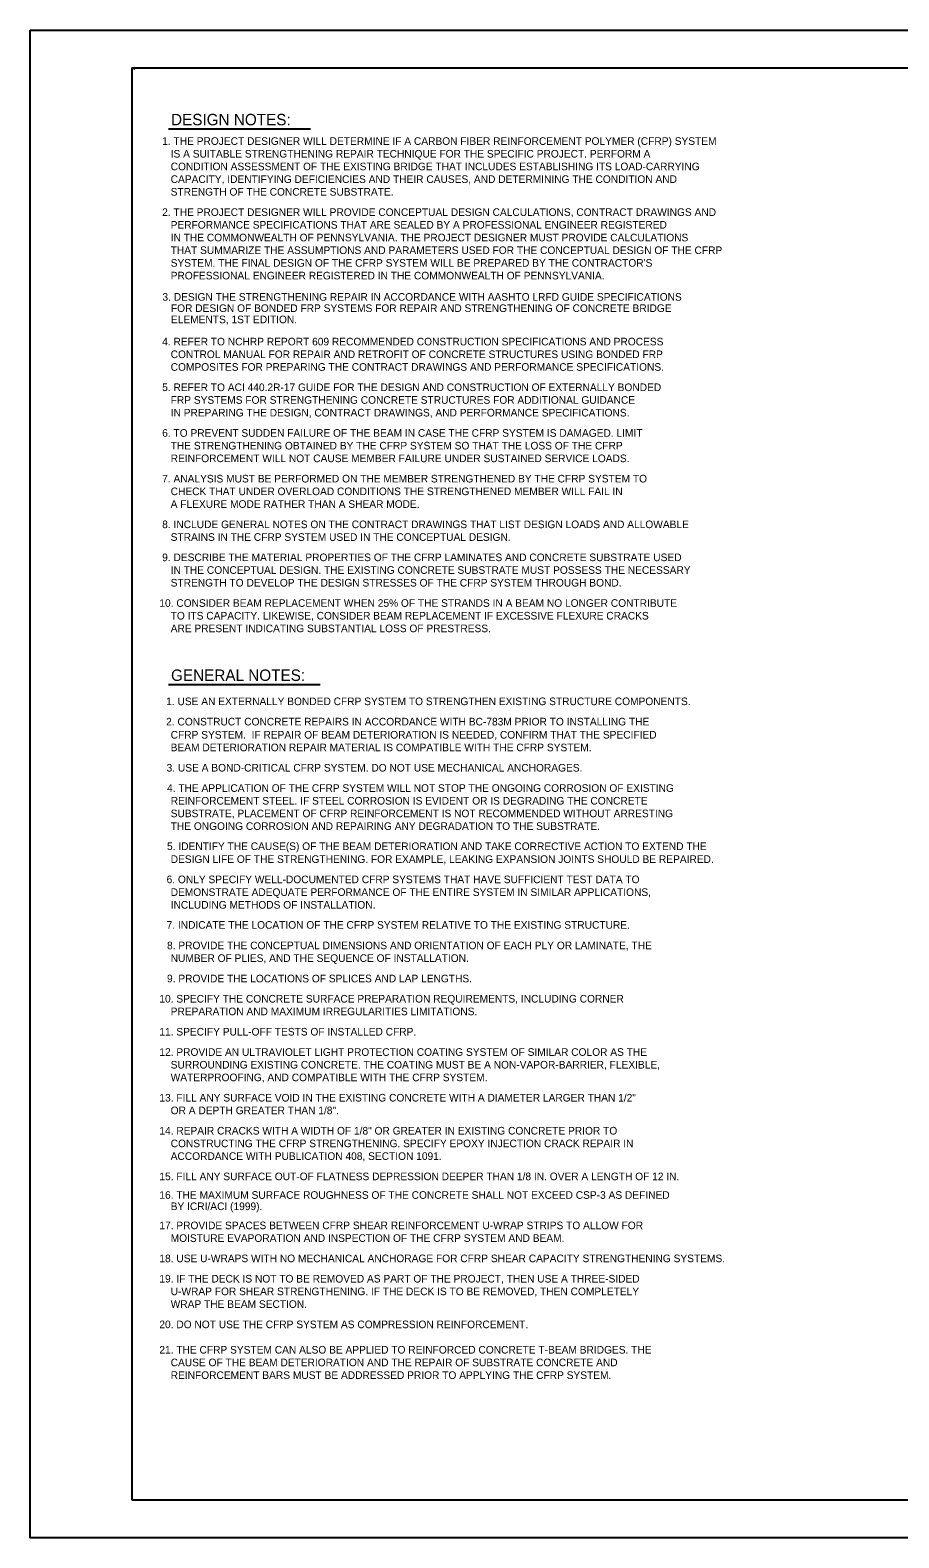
# Model space of a CAD drawing. Extents: x -875 to -19, y -633 to -39.
# Drawn here: x -875 to -532, y -633 to -39 of the extents above; entities that cross this region are included whole.
import ezdxf

# ---------------------------------------------------------------- set-up
doc = ezdxf.new("R2010")
doc.units = 0
for name, color, linetype in [('1', 7, 'Continuous'), ('2', 7, 'Continuous'), ('PLT-BNDY', 7, 'Continuous')]:
    doc.layers.add(name, color=color, linetype=linetype)

msp = doc.modelspace()

# ---------------------------------------------------------------- linework, layer by layer
at = {"layer": '1'}
for p, q in [((-48.54, -54.21), (-834.54, -54.21)), ((-834.54, -54.21), (-834.54, -618.21)), ((-834.54, -618.21), (-48.54, -618.21))]:
    msp.add_line(p, q, dxfattribs=at)
at = {"layer": '2'}
for p, q in [((-48.54, -54.21), (-834.54, -54.21)), ((-834.54, -54.89), (-834.54, -54.89)), ((-820.06, -78.13), (-764.06, -78.13)), ((-820.06, -297.01), (-760.25, -297.01))]:
    msp.add_line(p, q, dxfattribs=at)
msp.add_lwpolyline([(-833.19, -54.55), (-834.54, -54.21), (-833.19, -53.87)], dxfattribs=at)
at = {"layer": 'PLT-BNDY'}
msp.add_lwpolyline([(-874.54, -39.21), (-33.54, -39.21), (-33.54, -633.21), (-874.54, -633.21)], close=True, dxfattribs=at)

# ---------------------------------------------------------------- texts
at = {"layer": '2'}
for s, height, p in [('DESIGN NOTES:', 4.5, (-819.03, -76.69)), (' 1. THE PROJECT DESIGNER WILL DETERMINE IF A CARBON FIBER REINFORCEMENT POLYMER (CFRP) SYSTEM', 3, (-823.63, -84.41)), ('    IS A SUITABLE STRENGTHENING REPAIR TECHNIQUE FOR THE SPECIFIC PROJECT. PERFORM A', 3, (-823.63, -89.41)), ('    CONDITION ASSESSMENT OF THE EXISTING BRIDGE THAT INCLUDES ESTABLISHING ITS LOAD-CARRYING', 3, (-823.63, -94.41)), ('    CAPACITY, IDENTIFYING DEFICIENCIES AND THEIR CAUSES, AND DETERMINING THE CONDITION AND', 3, (-823.63, -99.41)), ('    STRENGTH OF THE CONCRETE SUBSTRATE.', 3, (-823.63, -104.41)), (' 2. THE PROJECT DESIGNER WILL PROVIDE CONCEPTUAL DESIGN CALCULATIONS, CONTRACT DRAWINGS AND', 3, (-823.63, -112.41)), ('    PERFORMANCE SPECIFICATIONS THAT ARE SEALED BY A PROFESSIONAL ENGINEER REGISTERED', 3, (-823.63, -117.41)), ('    THAT SUMMARIZE THE ASSUMPTIONS AND PARAMETERS USED FOR THE CONCEPTUAL DESIGN OF THE CFRP', 3, (-823.63, -127.41)), ('    IN THE COMMONWEALTH OF PENNSYLVANIA. THE PROJECT DESIGNER MUST PROVIDE CALCULATIONS', 3, (-823.63, -122.41)), ("    SYSTEM. THE FINAL DESIGN OF THE CFRP SYSTEM WILL BE PREPARED BY THE CONTRACTOR'S", 3, (-823.63, -132.41)), ('    PROFESSIONAL ENGINEER REGISTERED IN THE COMMONWEALTH OF PENNSYLVANIA.', 3, (-823.63, -137.41)), (' 3. DESIGN THE STRENGTHENING REPAIR IN ACCORDANCE WITH AASHTO LRFD GUIDE SPECIFICATIONS', 3, (-823.53, -145.8)), ('    FOR DESIGN OF BONDED FRP SYSTEMS FOR REPAIR AND STRENGTHENING OF CONCRETE BRIDGE', 3, (-823.53, -150.24)), ('    ELEMENTS, 1ST EDITION.', 3, (-823.53, -154.68)), (' 4. REFER TO NCHRP REPORT 609 RECOMMENDED CONSTRUCTION SPECIFICATIONS AND PROCESS', 3, (-823.63, -163.41)), ('    CONTROL MANUAL FOR REPAIR AND RETROFIT OF CONCRETE STRUCTURES USING BONDED FRP', 3, (-823.63, -168.41)), ('    COMPOSITES FOR PREPARING THE CONTRACT DRAWINGS AND PERFORMANCE SPECIFICATIONS.', 3, (-823.63, -173.41)), (' 5. REFER TO ACI 440.2R-17 GUIDE FOR THE DESIGN AND CONSTRUCTION OF EXTERNALLY BONDED', 3, (-823.63, -181.41)), ('    FRP SYSTEMS FOR STRENGTHENING CONCRETE STRUCTURES FOR ADDITIONAL GUIDANCE', 3, (-823.63, -186.41)), ('    IN PREPARING THE DESIGN, CONTRACT DRAWINGS, AND PERFORMANCE SPECIFICATIONS.', 3, (-823.63, -191.41)), (' 6. TO PREVENT SUDDEN FAILURE OF THE BEAM IN CASE THE CFRP SYSTEM IS DAMAGED. LIMIT', 3, (-823.63, -199.41)), ('    THE STRENGTHENING OBTAINED BY THE CFRP SYSTEM SO THAT THE LOSS OF THE CFRP', 3, (-823.63, -204.41)), ('    REINFORCEMENT WILL NOT CAUSE MEMBER FAILURE UNDER SUSTAINED SERVICE LOADS.', 3, (-823.63, -209.41)), (' 7. ANALYSIS MUST BE PERFORMED ON THE MEMBER STRENGTHENED BY THE CFRP SYSTEM TO', 3, (-823.63, -217.41)), ('    CHECK THAT UNDER OVERLOAD CONDITIONS THE STRENGTHENED MEMBER WILL FAIL IN', 3, (-823.63, -222.41)), ('    A FLEXURE MODE RATHER THAN A SHEAR MODE.', 3, (-823.63, -227.41)), (' 8. INCLUDE GENERAL NOTES ON THE CONTRACT DRAWINGS THAT LIST DESIGN LOADS AND ALLOWABLE', 3, (-823.63, -235.41)), ('    STRAINS IN THE CFRP SYSTEM USED IN THE CONCEPTUAL DESIGN.', 3, (-823.63, -240.41)), (' 9. DESCRIBE THE MATERIAL PROPERTIES OF THE CFRP LAMINATES AND CONCRETE SUBSTRATE USED', 3, (-823.63, -248.41)), ('    STRENGTH TO DEVELOP THE DESIGN STRESSES OF THE CFRP SYSTEM THROUGH BOND.', 3, (-823.63, -258.41)), ('    IN THE CONCEPTUAL DESIGN. THE EXISTING CONCRETE SUBSTRATE MUST POSSESS THE NECESSARY', 3, (-823.63, -253.41)), ('10. CONSIDER BEAM REPLACEMENT WHEN 25% OF THE STRANDS IN A BEAM NO LONGER CONTRIBUTE', 3, (-823.63, -266.41)), ('    TO ITS CAPACITY. LIKEWISE, CONSIDER BEAM REPLACEMENT IF EXCESSIVE FLEXURE CRACKS', 3, (-823.63, -271.41)), ('    ARE PRESENT INDICATING SUBSTANTIAL LOSS OF PRESTRESS. ', 3, (-823.63, -276.41)), ('GENERAL NOTES:', 4.5, (-819.03, -295.59)), ('1. USE AN EXTERNALLY BONDED CFRP SYSTEM TO STRENGTHEN EXISTING STRUCTURE COMPONENTS.', 3, (-820.95, -305.14)), ('2. CONSTRUCT CONCRETE REPAIRS IN ACCORDANCE WITH BC-783M PRIOR TO INSTALLING THE', 3, (-820.95, -313.14)), ('    CFRP SYSTEM.  IF REPAIR OF BEAM DETERIORATION IS NEEDED, CONFIRM THAT THE SPECIFIED', 3, (-823.63, -318.31)), ('    BEAM DETERIORATION REPAIR MATERIAL IS COMPATIBLE WITH THE CFRP SYSTEM.', 3, (-823.63, -323.31)), ('3. USE A BOND-CRITICAL CFRP SYSTEM. DO NOT USE MECHANICAL ANCHORAGES.', 3, (-820.78, -331.31)), ('4. THE APPLICATION OF THE CFRP SYSTEM WILL NOT STOP THE ONGOING CORROSION OF EXISTING', 3, (-820.61, -339.31)), ('    REINFORCEMENT STEEL. IF STEEL CORROSION IS EVIDENT OR IS DEGRADING THE CONCRETE', 3, (-823.63, -344.31)), ('    SUBSTRATE, PLACEMENT OF CFRP REINFORCEMENT IS NOT RECOMMENDED WITHOUT ARRESTING', 3, (-823.63, -349.31)), ('    THE ONGOING CORROSION AND REPAIRING ANY DEGRADATION TO THE SUBSTRATE.', 3, (-823.63, -354.31)), ('5. IDENTIFY THE CAUSE(S) OF THE BEAM DETERIORATION AND TAKE CORRECTIVE ACTION TO EXTEND THE', 3, (-820.61, -362.22)), ('    DESIGN LIFE OF THE STRENGTHENING. FOR EXAMPLE, LEAKING EXPANSION JOINTS SHOULD BE REPAIRED.', 3, (-823.63, -367.31)), ('6. ONLY SPECIFY WELL-DOCUMENTED CFRP SYSTEMS THAT HAVE SUFFICIENT TEST DATA TO', 3, (-820.78, -375.29)), ('    DEMONSTRATE ADEQUATE PERFORMANCE OF THE ENTIRE SYSTEM IN SIMILAR APPLICATIONS, ', 3, (-823.63, -380.31)), ('    INCLUDING METHODS OF INSTALLATION.', 3, (-823.63, -385.31)), ('7. INDICATE THE LOCATION OF THE CFRP SYSTEM RELATIVE TO THE EXISTING STRUCTURE.', 3, (-820.78, -393.23)), ('8. PROVIDE THE CONCEPTUAL DIMENSIONS AND ORIENTATION OF EACH PLY OR LAMINATE, THE', 3, (-820.61, -401.31)), ('    NUMBER OF PLIES, AND THE SEQUENCE OF INSTALLATION.', 3, (-823.63, -406.31)), ('9. PROVIDE THE LOCATIONS OF SPLICES AND LAP LENGTHS.', 3, (-820.61, -414.35)), ('10. SPECIFY THE CONCRETE SURFACE PREPARATION REQUIREMENTS, INCLUDING CORNER', 3, (-823.63, -422.31)), ('    PREPARATION AND MAXIMUM IRREGULARITIES LIMITATIONS.', 3, (-823.63, -427.31)), ('11. SPECIFY PULL-OFF TESTS OF INSTALLED CFRP.', 3, (-823.63, -435.31)), ('12. PROVIDE AN ULTRAVIOLET LIGHT PROTECTION COATING SYSTEM OF SIMILAR COLOR AS THE', 3, (-823.63, -443.31)), ('    SURROUNDING EXISTING CONCRETE. THE COATING MUST BE A NON-VAPOR-BARRIER, FLEXIBLE,', 3, (-823.63, -448.31)), ('    WATERPROOFING, AND COMPATIBLE WITH THE CFRP SYSTEM.', 3, (-823.63, -453.31)), ('13. FILL ANY SURFACE VOID IN THE EXISTING CONCRETE WITH A DIAMETER LARGER THAN 1/2"', 3, (-823.63, -461.31)), ('    OR A DEPTH GREATER THAN 1/8".', 3, (-823.63, -466.31)), ('14. REPAIR CRACKS WITH A WIDTH OF 1/8" OR GREATER IN EXISTING CONCRETE PRIOR TO', 3, (-823.63, -474.31)), ('    CONSTRUCTING THE CFRP STRENGTHENING. SPECIFY EPOXY INJECTION CRACK REPAIR IN', 3, (-823.63, -479.31)), ('    ACCORDANCE WITH PUBLICATION 408, SECTION 1091.', 3, (-823.63, -484.31)), ('15. FILL ANY SURFACE OUT-OF FLATNESS DEPRESSION DEEPER THAN 1/8 IN. OVER A LENGTH OF 12 IN.', 3, (-823.63, -492.31)), ('16. THE MAXIMUM SURFACE ROUGHNESS OF THE CONCRETE SHALL NOT EXCEED CSP-3 AS DEFINED', 3, (-823.63, -499.64)), ('    BY ICRI/ACI (1999).', 3, (-823.63, -504.08)), ('17. PROVIDE SPACES BETWEEN CFRP SHEAR REINFORCEMENT U-WRAP STRIPS TO ALLOW FOR', 3, (-823.63, -511.61)), ('    MOISTURE EVAPORATION AND INSPECTION OF THE CFRP SYSTEM AND BEAM.', 3, (-823.63, -516.61)), ('18. USE U-WRAPS WITH NO MECHANICAL ANCHORAGE FOR CFRP SHEAR CAPACITY STRENGTHENING SYSTEMS.', 3, (-823.63, -524.61)), ('19. IF THE DECK IS NOT TO BE REMOVED AS PART OF THE PROJECT, THEN USE A THREE-SIDED', 3, (-823.63, -532.61)), ('    U-WRAP FOR SHEAR STRENGTHENING. IF THE DECK IS TO BE REMOVED, THEN COMPLETELY', 3, (-823.63, -537.61)), ('    WRAP THE BEAM SECTION.', 3, (-823.63, -542.61)), ('20. DO NOT USE THE CFRP SYSTEM AS COMPRESSION REINFORCEMENT.', 3, (-823.63, -550.61)), ('21. THE CFRP SYSTEM CAN ALSO BE APPLIED TO REINFORCED CONCRETE T-BEAM BRIDGES. THE', 3, (-823.63, -560.61)), ('    CAUSE OF THE BEAM DETERIORATION AND THE REPAIR OF SUBSTRATE CONCRETE AND', 3, (-823.63, -565.61)), ('    REINFORCEMENT BARS MUST BE ADDRESSED PRIOR TO APPLYING THE CFRP SYSTEM.', 3, (-823.63, -570.61))]:
    msp.add_text(s, height=height, dxfattribs=at).set_placement(p)

doc.saveas('drawing.dxf')
